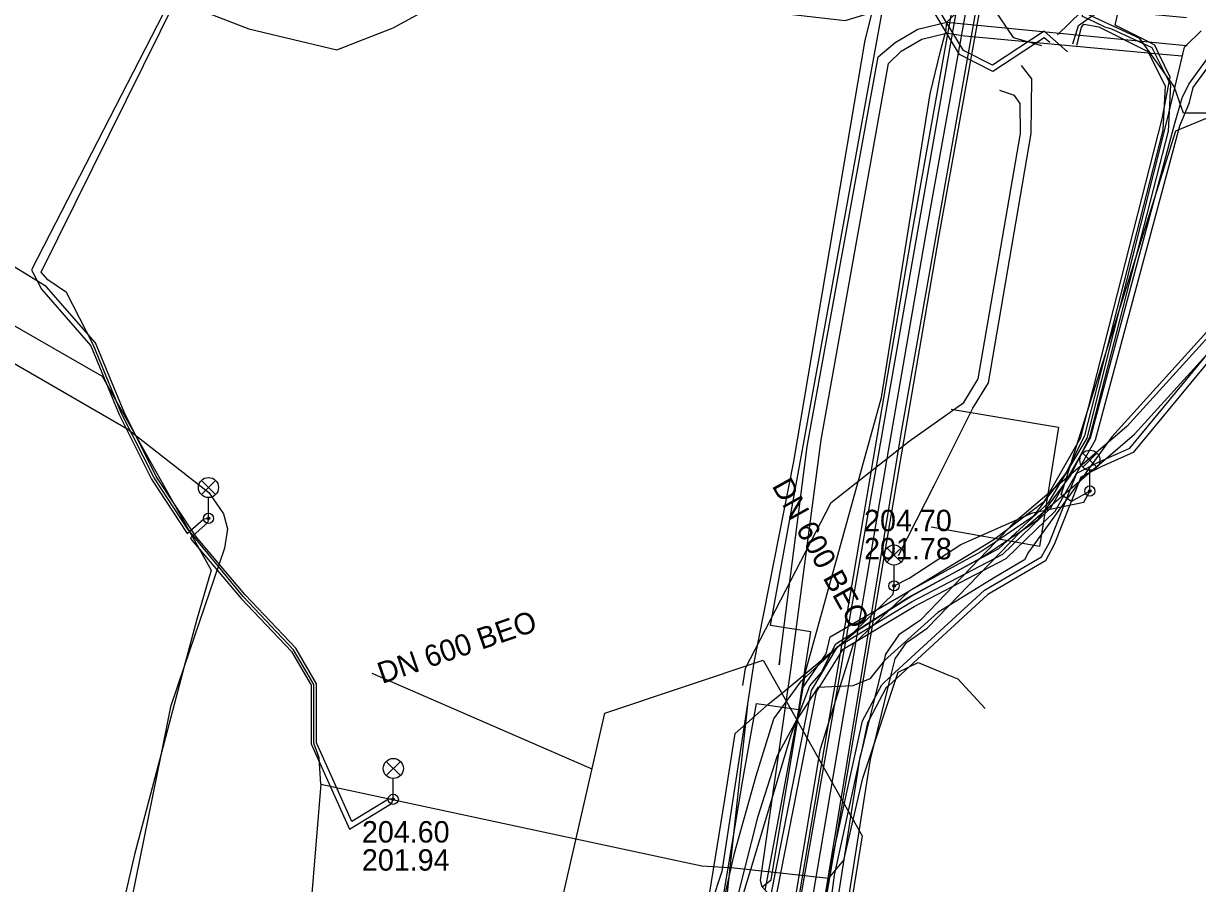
# Model space of a CAD drawing. Extents: x -596228 to -595156, y -1161235 to -1159373.
# Drawn here: x -595884.93 to -595841.11, y -1160051.93 to -1160019.81 of the extents above; entities that cross this region are included whole.
import ezdxf

# ---------------------------------------------------------------- set-up
doc = ezdxf.new("R2010")
doc.units = 0
for name, color, linetype in [('Vrstva 1', 7, 'Continuous'), ('Vrstva 12', 7, 'Continuous'), ('Vrstva 14', 7, 'Continuous'), ('Vrstva 25', 7, 'Continuous'), ('Vrstva 26', 7, 'Continuous'), ('Vrstva 29', 7, 'Continuous'), ('Vrstva 33', 7, 'Continuous'), ('Vrstva 4', 7, 'Continuous'), ('Vrstva 42', 7, 'Continuous'), ('Vrstva 44', 7, 'Continuous'), ('Vrstva 53', 7, 'Continuous'), ('Vrstva 55', 7, 'Continuous')]:
    doc.layers.add(name, color=color, linetype=linetype)

msp = doc.modelspace()

# ---------------------------------------------------------------- linework, layer by layer
at = {"layer": 'Vrstva 1'}
for p, q in [((-595863.23, -1160045.57), (-595857.33, -1160043.59)), ((-595857.33, -1160043.59), (-595853.63, -1160050.15)), ((-595871.93, -1160044.07), (-595863.72, -1160047.64)), ((-595878.63, -1160112.85), (-595863.23, -1160045.57)), ((-595853.63, -1160050.15), (-595860.88, -1160094.77))]:
    msp.add_line(p, q, dxfattribs=at)
at = {"layer": 'Vrstva 12'}
for points in [[(-595874.36, -1160044.04), (-595874.85, -1160043.2), (-595876.74, -1160041.21), (-595878.8, -1160038.7), (-595880.06, -1160036.78), (-595881.27, -1160034.37), (-595882.33, -1160031.8), (-595883.33, -1160029.86), (-595884.03, -1160029.39), (-595884.28, -1160029.1), (-595877.9, -1160016.22), (-595876.79, -1160015.92)], [(-595873.83, -1160048.21), (-595859.61, -1160051.26), (-595858.41, -1160051.34), (-595854.87, -1160051.72), (-595854.31, -1160051.05), (-595853.61, -1160047.99), (-595852.29, -1160044.03), (-595851.54, -1160043.67), (-595850.43, -1160044.13)], [(-595873.83, -1160048.21), (-595873.9, -1160047.23), (-595874.1, -1160046.69), (-595874.1, -1160044.49), (-595874.36, -1160044.04)], [(-595850.431, -1160044.132), (-595850.054, -1160044.287), (-595849.04, -1160045.393)], [(-595873.83, -1160048.21), (-595874.58, -1160057.28), (-595878.97, -1160081.97), (-595886.34, -1160124.44), (-595887.99, -1160133.91), (-595889.12, -1160140.39), (-595891.94, -1160156.53), (-595892.78, -1160161.36), (-595893.73, -1160166.74)]]:
    msp.add_lwpolyline(points, dxfattribs=at)
at = {"layer": 'Vrstva 14'}
msp.add_lwpolyline([(-595903.525, -1160327.591), (-595903.438, -1160327.11), (-595895.992, -1160276.218), (-595895.362, -1160271.913), (-595894.416, -1160266.829), (-595893.077, -1160257.958), (-595892.847, -1160256.335), (-595887.94, -1160223.167), (-595881.65, -1160186.81), (-595876.814, -1160159.541), (-595869.649, -1160117.522), (-595863.209, -1160078.856), (-595858.091, -1160048.124), (-595857.576, -1160045.207), (-595855.994, -1160045.422), (-595855.543, -1160042.523), (-595857.05, -1160042.292), (-595850.5, -1160006.311), (-595840.026, -1160007.969)], dxfattribs=at)
at = {"layer": 'Vrstva 25'}
msp.add_lwpolyline([(-595848.913, -1160014.604), (-595851.258, -1160027.646), (-595852.717, -1160036.135), (-595854.448, -1160046.34), (-595856.426, -1160058.005), (-595858.649, -1160070.917), (-595847.414, -1160073.01)], dxfattribs=at)
at = {"layer": 'Vrstva 26'}
for points in [[(-595848.334, -1160014.211), (-595850.766, -1160027.733), (-595852.224, -1160036.219), (-595853.955, -1160046.424), (-595855.933, -1160058.089), (-595858.073, -1160070.515), (-595847.323, -1160072.519)], [(-595847.898, -1160073.429), (-595859.226, -1160071.318), (-595856.918, -1160057.921), (-595854.941, -1160046.256), (-595853.21, -1160036.051), (-595851.751, -1160027.56), (-595849.492, -1160014.998)]]:
    msp.add_lwpolyline(points, dxfattribs=at)
at = {"layer": 'Vrstva 29'}
msp.add_lwpolyline([(-595850.313, -1160034.216), (-595846.303, -1160034.881), (-595847.007, -1160039.338), (-595851.052, -1160038.624)], dxfattribs=at)
at = {"layer": 'Vrstva 33'}
for p, q in [((-595845.395, -1160035.855), (-595844.865, -1160036.385)), ((-595845.395, -1160036.385), (-595844.865, -1160035.855)), ((-595845.13, -1160037.27), (-595845.13, -1160036.495)), ((-595878.295, -1160036.875), (-595877.765, -1160037.405)), ((-595878.295, -1160037.405), (-595877.765, -1160036.875)), ((-595878.03, -1160038.29), (-595878.03, -1160037.515)), ((-595852.705, -1160039.395), (-595852.175, -1160039.925)), ((-595852.705, -1160039.925), (-595852.175, -1160039.395)), ((-595852.44, -1160040.81), (-595852.44, -1160040.035)), ((-595871.395, -1160047.365), (-595870.865, -1160047.895)), ((-595871.395, -1160047.895), (-595870.865, -1160047.365)), ((-595871.13, -1160048.78), (-595871.13, -1160048.005))]:
    msp.add_line(p, q, dxfattribs=at)
for centre, radius in [((-595845.13, -1160036.12), 0.375), ((-595878.03, -1160037.14), 0.375), ((-595845.13, -1160037.27), 0.19), ((-595845.13, -1160037.27), 0.05), ((-595878.03, -1160038.29), 0.19), ((-595878.03, -1160038.29), 0.05), ((-595852.44, -1160039.66), 0.375), ((-595852.44, -1160040.81), 0.19), ((-595852.44, -1160040.81), 0.05), ((-595871.13, -1160047.63), 0.375), ((-595871.13, -1160048.78), 0.19), ((-595871.13, -1160048.78), 0.05)]:
    msp.add_circle(centre, radius, dxfattribs=at)
at = {"layer": 'Vrstva 42'}
for points in [[(-595873.688, -1159960.969), (-595873.136, -1159957.91), (-595871.902, -1159958.088), (-595863.25, -1159959.53), (-595863.9, -1159965.29), (-595865.673, -1159976.949), (-595867.053, -1159989.854), (-595868.25, -1159989.709), (-595873.971, -1159989.019), (-595874.999, -1159988.861), (-595876.151, -1159992.513), (-595876.588, -1159993.79), (-595863.441, -1159998.192), (-595865.906, -1160011.02), (-595857.067, -1160012.572), (-595848.508, -1160014.294), (-595852.168, -1160035.065), (-595855.053, -1160052.565), (-595858.203, -1160070.6), (-595847.46, -1160072.642), (-595848.325, -1160077.311)], [(-595916.617, -1159981.581), (-595914.21, -1159982.379), (-595897.57, -1159987.853), (-595877.263, -1159994.535), (-595864.428, -1159998.802), (-595866.813, -1160011.736), (-595857.199, -1160013.352), (-595849.351, -1160014.93), (-595853.123, -1160036.433), (-595855.896, -1160052.235), (-595859.081, -1160071.227), (-595847.219, -1160073.379), (-595833.399, -1160075.892)], [(-595845.762, -1160020.574), (-595845.555, -1160019.886), (-595845.208, -1160019.645), (-595845.045, -1160019.532), (-595845.03, -1160019.524), (-595844.385, -1160019.156), (-595843.73, -1160017.924), (-595843.051, -1160014.089), (-595842.778, -1160012.547), (-595842.827, -1160011.807), (-595843.287, -1160011.102), (-595843.367, -1160010.98), (-595843.592, -1160010.916), (-595845.626, -1160010.338), (-595849.998, -1160009.521), (-595850.984, -1160008.975), (-595851.071, -1160008.648), (-595850.899, -1160006.108), (-595848.916, -1159992.029)], [(-595844.58, -1160019.94), (-595845.208, -1160019.645), (-595845.41, -1160019.55), (-595845.3, -1160018.65), (-595843.83, -1160016.13), (-595843.807, -1160016.071), (-595843.051, -1160014.089), (-595842.62, -1160012.96), (-595842.8, -1160011.4), (-595843.287, -1160011.102), (-595843.592, -1160010.916), (-595844.06, -1160010.63), (-595847.51, -1160009.81), (-595848.43, -1160009.2), (-595848.66, -1160008.41), (-595847.04, -1160000.74)], [(-595925.809, -1160010.705), (-595913.032, -1160008.486), (-595906.04, -1160009.646), (-595896.533, -1160012.291), (-595876.524, -1160020.016), (-595873.234, -1160020.793), (-595871.135, -1160019.978), (-595868.5, -1160018.526), (-595864.388, -1160018.532), (-595854.268, -1160019.7), (-595853.479, -1160019.468), (-595852.989, -1160018.938), (-595851.829, -1160018.233), (-595848.755, -1160019.21), (-595847.99, -1160020.336), (-595846.934, -1160020.638)], [(-595844.58, -1160019.94), (-595844.319, -1160020.018), (-595842.82, -1160020.704), (-595842.116, -1160022.101), (-595842.208, -1160023.828), (-595845.14, -1160035.264), (-595845.822, -1160036.64), (-595845.836, -1160036.668), (-595846.871, -1160038.062), (-595847.1, -1160038.371), (-595847.723, -1160038.79), (-595849.1, -1160039.717), (-595849.251, -1160039.8), (-595851.766, -1160041.179), (-595852.648, -1160041.748), (-595853.883, -1160042.545), (-595856.585, -1160044.806), (-595857.194, -1160045.288)], [(-595845.611, -1160020.624), (-595845.441, -1160019.946), (-595845.359, -1160019.843), (-595844.794, -1160019.94), (-595842.968, -1160020.854), (-595842.318, -1160022.143), (-595842.406, -1160023.798), (-595845.328, -1160035.194), (-595846.008, -1160036.564), (-595846.483, -1160037.205), (-595847.24, -1160038.225), (-595848.641, -1160039.167), (-595849.204, -1160039.545), (-595851.862, -1160041.003)], [(-595852.272, -1160039.677), (-595850.93, -1160037.037), (-595849.493, -1160034.175), (-595848.914, -1160033.23), (-595847.32, -1160023.92), (-595847.302, -1160021.877), (-595847.687, -1160021.386)], [(-595858.082, -1160044.528), (-595857.98, -1160043.886), (-595854.792, -1160037.693), (-595851.871, -1160035.411), (-595849.835, -1160033.965), (-595849.296, -1160033.086), (-595847.718, -1160023.918), (-595847.733, -1160022.797), (-595847.939, -1160022.504), (-595848.492, -1160022.32)], [(-595836.395, -1160026.754), (-595843.744, -1160034.864), (-595845.822, -1160036.64), (-595846.483, -1160037.205), (-595847.999, -1160038.5), (-595848.641, -1160039.167), (-595849.251, -1160039.8), (-595851.457, -1160042.09), (-595852.264, -1160042.643), (-595852.761, -1160043.366), (-595853.168, -1160045.013), (-595853.366, -1160045.813), (-595853.671, -1160047.045), (-595853.711, -1160047.209), (-595853.723, -1160047.284), (-595855.486, -1160058.519)], [(-595837.694, -1160028.783), (-595843.518, -1160035.832), (-595844.677, -1160036.35), (-595845.151, -1160036.593), (-595845.461, -1160036.752), (-595845.524, -1160036.912), (-595846.459, -1160039.272), (-595846.786, -1160039.872), (-595848.94, -1160041.131), (-595852.64, -1160044.54), (-595852.74, -1160044.632), (-595853.366, -1160045.813), (-595853.425, -1160045.925), (-595853.671, -1160047.045), (-595853.723, -1160047.284), (-595854.671, -1160051.617), (-595855.572, -1160058.309)], [(-595855.768, -1160058.271), (-595854.869, -1160051.583), (-595853.615, -1160045.855), (-595853.168, -1160045.013), (-595852.9, -1160044.508), (-595852.553, -1160044.188), (-595849.06, -1160040.969), (-595846.935, -1160039.728), (-595846.641, -1160039.188), (-595845.849, -1160037.19), (-595845.619, -1160036.608), (-595844.763, -1160036.17), (-595844.537, -1160036.068), (-595843.642, -1160035.668), (-595840.642, -1160032.037)], [(-595855.096, -1160058.611), (-595853.319, -1160047.289), (-595852.64, -1160044.54), (-595852.553, -1160044.188), (-595852.391, -1160043.532), (-595851.976, -1160042.931), (-595851.197, -1160042.396), (-595847.725, -1160038.792), (-595847.723, -1160038.79), (-595846.871, -1160038.062), (-595845.849, -1160037.19), (-595845.524, -1160036.912), (-595845.151, -1160036.593), (-595844.537, -1160036.068), (-595843.464, -1160035.152), (-595840.642, -1160032.037)], [(-595852.082, -1160085.098), (-595852.831, -1160085.013), (-595854.172, -1160084.86), (-595854.297, -1160084.763), (-595855.384, -1160083.917), (-595856.047, -1160083.842), (-595857.906, -1160083.223), (-595860.075, -1160082.16), (-595860.444, -1160081.979), (-595860.763, -1160081.822), (-595860.932, -1160080.592), (-595859.753, -1160073.316), (-595858.179, -1160064.287), (-595857.105, -1160058.32), (-595855.189, -1160046.9), (-595853.954, -1160042.986), (-595852.648, -1160041.748), (-595851.862, -1160041.003)], [(-595860.238, -1160057.936), (-595858.755, -1160048.787), (-595858.366, -1160046.324), (-595857.194, -1160045.288)]]:
    msp.add_lwpolyline(points, dxfattribs=at)
at = {"layer": 'Vrstva 44'}
for points in [[(-595859.242, -1160052.634), (-595858.859, -1160051.464), (-595857.661, -1160043.675), (-595856.174, -1160036.17), (-595853.523, -1160020.441), (-595852.577, -1160016.681), (-595852.517, -1160016.249), (-595851.566, -1160009.432), (-595851.43, -1160007.963), (-595850.96, -1160002.864), (-595850.926, -1160002.583)], [(-595857.245, -1160052.174), (-595857.198, -1160051.924), (-595856.052, -1160045.776), (-595855.832, -1160044.598), (-595855.828, -1160044.592), (-595854.97, -1160043.348), (-595854.829, -1160042.718), (-595852.015, -1160041.08), (-595848.715, -1160039.078), (-595846.828, -1160037.651), (-595845.464, -1160035.271), (-595842.427, -1160023.367), (-595842.135, -1160021.812), (-595842.55, -1160020.946), (-595842.708, -1160020.617), (-595842.943, -1160020.499), (-595844.18, -1160019.88), (-595844.062, -1160019.324), (-595843.92, -1160018.66)], [(-595857.364, -1160052.049), (-595857.198, -1160051.924), (-595857.022, -1160051.79), (-595856.003, -1160045.65), (-595855.828, -1160044.592), (-595855.719, -1160043.937), (-595852.904, -1160033.783), (-595851.088, -1160022.445), (-595850.706, -1160020.852), (-595850.525, -1160020.192), (-595850.509, -1160020.132), (-595850.466, -1160019.768), (-595850.194, -1160019.495), (-595849.839, -1160019.271), (-595846.696, -1160018.952), (-595845.92, -1160019.062), (-595844.062, -1160019.324), (-595843.477, -1160019.407), (-595841.518, -1160019.59)], [(-595856.703, -1160043.566), (-595856.732, -1160043.766), (-595855.685, -1160035.608), (-595853.031, -1160021.057), (-595852.402, -1160020.523), (-595851.556, -1160020.021), (-595850.466, -1160019.768), (-595842.943, -1160020.499), (-595841.535, -1160020.636), (-595841.496, -1160020.64)], [(-595855.58, -1160044.55), (-595855.16, -1160044.06), (-595854.609, -1160042.97), (-595851.934, -1160041.252), (-595848.532, -1160039.415), (-595846.674, -1160037.712), (-595845.231, -1160035.298), (-595842.243, -1160023.422), (-595841.6, -1160020.7), (-595841.535, -1160020.636), (-595840.98, -1160020.09)], [(-595917.145, -1160021.336), (-595907.831, -1160020.234), (-595904.592, -1160020.509), (-595901.244, -1160021.926), (-595881.998, -1160032.976), (-595880.757, -1160035.185), (-595877.925, -1160040.228), (-595878.48, -1160042.11), (-595878.933, -1160043.824), (-595879.809, -1160047.133), (-595880.79, -1160050.84), (-595882.06, -1160056.34)], [(-595858.401, -1160057.773), (-595858.18, -1160057.213), (-595857.755, -1160056.136), (-595857.586, -1160055.707), (-595857.029, -1160053.114), (-595856.931, -1160052.504), (-595857.035, -1160052.395), (-595857.245, -1160052.174), (-595857.364, -1160052.049), (-595857.365, -1160052.048), (-595857.43, -1160051.816), (-595856.979, -1160048.701), (-595856.277, -1160043.862), (-595855.165, -1160035.357), (-595852.649, -1160021.312), (-595852.169, -1160020.85), (-595851.405, -1160020.397), (-595850.525, -1160020.192), (-595850.443, -1160020.173), (-595849.791, -1160020.273), (-595842.55, -1160020.946), (-595841.682, -1160021.027)], [(-595841.441, -1160022.081), (-595840.052, -1160020.177)], [(-595912.272, -1160021.527), (-595907.24, -1160020.645), (-595904.592, -1160021.408), (-595897.312, -1160025.648), (-595890.456, -1160029.276), (-595887.525, -1160031.208), (-595881.038, -1160034.966), (-595880.757, -1160035.185), (-595878.02, -1160037.323), (-595877.468, -1160038.12), (-595877.324, -1160038.678), (-595877.43, -1160039.4), (-595878.933, -1160043.824), (-595879.445, -1160045.329), (-595879.809, -1160047.133), (-595880.898, -1160052.528)], [(-595841.279, -1160022.199), (-595840.409, -1160021.009)], [(-595843.312, -1160065.292), (-595846.656, -1160065.967), (-595847.396, -1160066.117), (-595850.608, -1160066.765), (-595855.392, -1160066.081), (-595858.609, -1160065.695), (-595858.732, -1160065.442), (-595859.097, -1160064.695), (-595858.842, -1160063.28), (-595857.375, -1160055.152), (-595855.334, -1160044.772), (-595854.342, -1160043.176), (-595851.692, -1160041.584), (-595848.26, -1160039.792), (-595846.43, -1160038.018), (-595844.919, -1160035.362), (-595841.777, -1160023.635), (-595841.41, -1160022.76), (-595841.279, -1160022.199)], [(-595857.035, -1160052.395), (-595855.524, -1160044.718), (-595854.545, -1160043.093), (-595851.792, -1160041.41), (-595848.378, -1160039.628), (-595846.59, -1160037.894), (-595845.105, -1160035.286), (-595841.969, -1160023.579), (-595841.68, -1160022.59), (-595841.441, -1160022.081)], [(-595867.55, -1160097.7), (-595865.77, -1160088.25), (-595865.01, -1160083.51), (-595864.31, -1160080.03), (-595863.56, -1160076.52), (-595862.55, -1160070.62), (-595861.798, -1160065.97), (-595861.691, -1160065.304), (-595861.59, -1160064.68), (-595860.375, -1160060.257), (-595859.871, -1160058.422), (-595859.737, -1160057.936), (-595859.45, -1160056.89), (-595858.987, -1160055.362), (-595857.7, -1160051.11), (-595856.979, -1160048.701), (-595856.28, -1160046.37), (-595856.052, -1160045.776), (-595856.003, -1160045.65), (-595855.58, -1160044.55)], [(-595877.641, -1160157.25), (-595877.206, -1160154.877), (-595875.823, -1160146.872), (-595874.194, -1160137.323), (-595870.493, -1160116.878), (-595869.152, -1160108.721), (-595866.815, -1160096.285), (-595864.579, -1160081.663), (-595862.969, -1160076.234), (-595861.913, -1160073.61), (-595860.434, -1160067.371), (-595860.472, -1160066.199), (-595860.336, -1160065.565), (-595860.108, -1160064.5), (-595859.919, -1160062.97), (-595859.588, -1160060.589), (-595859.432, -1160059.468), (-595859.081, -1160056.226), (-595858.987, -1160055.362), (-595857.892, -1160045.25)]]:
    msp.add_lwpolyline(points, dxfattribs=at)
at = {"layer": 'Vrstva 53'}
msp.add_lwpolyline([(-595834.49, -1160024.39), (-595844.31, -1160035.25), (-595847.42, -1160039.55), (-595847.57, -1160039.84), (-595848.73, -1160040.53), (-595850.81, -1160041.8), (-595852.8, -1160043.6), (-595853.34, -1160044.28), (-595853.98, -1160044.54), (-595855.28, -1160044.61), (-595856.08, -1160045.82), (-595856.8, -1160047.16), (-595857.54, -1160049.46), (-595859.63, -1160057.71), (-595861.65, -1160065.98), (-595862.86, -1160074.22), (-595864.25, -1160082.03), (-595866.66, -1160096.08), (-595868.31, -1160105.61), (-595869.84, -1160114.54), (-595871.58, -1160124.29), (-595873.02, -1160132.72), (-595874.46, -1160140.81), (-595876.52, -1160152.45)], dxfattribs=at)
at = {"layer": 'Vrstva 55'}
for points in [[(-595845.97, -1160020.87), (-595846.83, -1160020.1), (-595848.76, -1160021.37), (-595849.85, -1160020.82), (-595850.84, -1160019.18), (-595851.44, -1160017.15), (-595851.76, -1160016.69), (-595852.42, -1160013.86), (-595852.46, -1160011.55), (-595852.03, -1160008.12), (-595850.88, -1159998.12), (-595849.48, -1159988.03), (-595850.06, -1159987.59)], [(-595878.15, -1160016.39), (-595884.64, -1160029.01), (-595884.26, -1160029.73), (-595882.42, -1160031.85), (-595881.36, -1160034.41), (-595880.15, -1160036.83), (-595878.82, -1160038.85), (-595878.2, -1160038.31), (-595878.03, -1160038.29), (-595878.07, -1160038.46), (-595878.7, -1160039.02), (-595878.65, -1160039.1), (-595876.81, -1160041.28), (-595874.93, -1160043.26), (-595874.2, -1160044.52), (-595874.2, -1160046.71), (-595872.76, -1160049.89), (-595871.2, -1160048.94), (-595871.13, -1160048.78), (-595871.31, -1160048.77), (-595872.68, -1160049.61), (-595874, -1160046.67), (-595874, -1160044.47), (-595874.77, -1160043.14), (-595876.66, -1160041.15), (-595878.49, -1160038.98), (-595879.98, -1160036.73), (-595881.18, -1160034.33), (-595882.25, -1160031.74), (-595884.09, -1160029.63), (-595885.84, -1160028.56)], [(-595846.62, -1160020.52), (-595846.84, -1160020.35), (-595848.75, -1160021.6), (-595849.99, -1160020.97), (-595851.02, -1160019.26)], [(-595840.53, -1160023.16), (-595841.63, -1160023.16), (-595841.98, -1160022.17), (-595843.27, -1160020.37), (-595845.44, -1160019.37), (-595846.34, -1160020.24)], [(-595862.06, -1160062.41), (-595861.87, -1160062.51), (-595861.08, -1160062.38), (-595859.65, -1160056.34), (-595860.21, -1160055.99), (-595859.5, -1160055.71), (-595858.4, -1160050.79), (-595857.59, -1160047.91), (-595856.92, -1160045.78), (-595855.89, -1160044.36), (-595854.2, -1160042.79), (-595852.47, -1160041.12), (-595852.44, -1160040.81), (-595851.88, -1160040.53), (-595849.94, -1160039.27), (-595847.27, -1160038.08), (-595845.36, -1160037.68), (-595845.13, -1160037.27), (-595845.81, -1160037.66), (-595846.2, -1160037.41), (-595841.92, -1160023.82), (-595839.99, -1160023.02)]]:
    msp.add_lwpolyline(points, dxfattribs=at)

# ---------------------------------------------------------------- texts
at = {"layer": 'Vrstva 4'}
for rotation, p in [(299, (-595857.015, -1160037.074)), (19, (-595871.55, -1160044.479))]:
    msp.add_text('DN 600 BEO', height=0.8, rotation=rotation, dxfattribs=at).set_placement(p)
for s, p in [('204.70', (-595853.557, -1160038.77)), ('201.78', (-595853.557, -1160039.82)), ('204.60', (-595872.301, -1160050.395)), ('201.94', (-595872.301, -1160051.445))]:
    msp.add_text(s, height=0.8, dxfattribs=at).set_placement(p)

doc.saveas('drawing.dxf')
